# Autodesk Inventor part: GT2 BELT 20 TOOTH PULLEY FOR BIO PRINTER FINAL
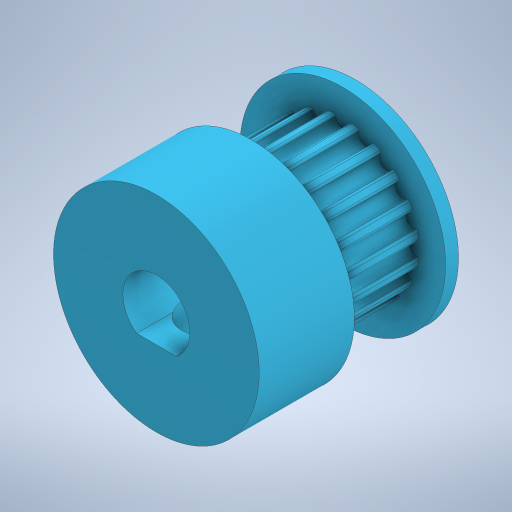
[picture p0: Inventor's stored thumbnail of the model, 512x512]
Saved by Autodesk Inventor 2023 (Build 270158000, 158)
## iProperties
Created: 2025-07
Part Number: GT2 BELT 20 TOOTH PULLEY FOR BIO PRINTER FINAL
Material: Generic
Document SubType Name: Modeling
Designer: erjon
Density: 1 g/cm^3
Appearance: Default
Author: erjon
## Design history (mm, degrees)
sketch "Sketch1" dims "d0" = 11.9
  geometry: L1 (0, 5.95)-(0, 5.2); L2 (0, 5.2)-(0, 5.755); C1 r 0.15 at (-0.705, 5.757); C2 r 0.15 at (-1.109, 5.693); C3 r 0.15 at (-2.45, 5.257); C4 r 0.15 at (-2.814, 5.072); C5 r 0.15 at (-3.954, 4.243); C6 r 0.15 at (-4.243, 3.954); C7 r 0.15 at (-5.072, 2.814); C8 r 0.15 at (-5.257, 2.45); C9 r 0.15 at (-5.693, 1.109); C10 r 0.15 at (-5.757, 0.705); C11 r 0.15 at (-5.757, -0.705); C12 r 0.15 at (-5.693, -1.109); C13 r 0.15 at (-5.257, -2.45); C14 r 0.15 at (-5.072, -2.814); C15 r 0.15 at (-4.243, -3.954); C16 r 0.15 at (-3.954, -4.243); C17 r 0.15 at (-2.814, -5.072); C18 r 0.15 at (-2.45, -5.257); C19 r 0.15 at (-1.109, -5.693); C20 r 0.15 at (-0.705, -5.757); C21 r 0.15 at (0.705, -5.757); C22 r 0.15 at (1.109, -5.693); C23 r 0.15 at (2.45, -5.257); C24 r 0.15 at (2.814, -5.072); C25 r 0.15 at (3.954, -4.243); C26 r 0.15 at (4.243, -3.954); C27 r 0.15 at (5.072, -2.814); C28 r 0.15 at (5.257, -2.45); C29 r 0.15 at (5.693, -1.109); C30 r 0.15 at (5.757, -0.705); C31 r 0.15 at (5.757, 0.705); C32 r 0.15 at (5.693, 1.109); C33 r 0.15 at (5.257, 2.45); C34 r 0.15 at (5.072, 2.814); C35 r 0.15 at (4.243, 3.954); C36 r 0.15 at (3.954, 4.243); C37 r 0.15 at (2.814, 5.072); C38 r 0.15 at (2.45, 5.257); C39 r 0.15 at (1.109, 5.693); C40 r 0.15 at (0.705, 5.757); A1 r 0.555 centre (0, 5.755) between (-0.528, 5.927) and (0.528, 5.927); A2 r 0.555 centre (-1.778, 5.473) between (-2.333, 5.473) and (-1.329, 5.8); A3 r 0.555 centre (-3.383, 4.656) between (-3.911, 4.484) and (-3.057, 5.105); A4 r 0.555 centre (-4.656, 3.383) between (-5.105, 3.057) and (-4.484, 3.911); A5 r 0.555 centre (-5.473, 1.778) between (-5.8, 1.329) and (-5.473, 2.333); A6 r 0.555 centre (-5.755, 0) between (-5.927, -0.528) and (-5.927, 0.528); A7 r 0.555 centre (-5.473, -1.778) between (-5.473, -2.333) and (-5.8, -1.329); A8 r 0.555 centre (-4.656, -3.383) between (-4.484, -3.911) and (-5.105, -3.057); A9 r 0.555 centre (-3.383, -4.656) between (-3.057, -5.105) and (-3.911, -4.484); A10 r 0.555 centre (-1.778, -5.473) between (-1.329, -5.8) and (-2.333, -5.473); A11 r 0.555 centre (0, -5.755) between (0.528, -5.927) and (-0.528, -5.927); A12 r 0.555 centre (1.778, -5.473) between (2.333, -5.473) and (1.329, -5.8); A13 r 0.555 centre (3.383, -4.656) between (3.911, -4.484) and (3.057, -5.105); A14 r 0.555 centre (4.656, -3.383) between (5.105, -3.057) and (4.484, -3.911); A15 r 0.555 centre (5.473, -1.778) between (5.8, -1.329) and (5.473, -2.333); A16 r 0.555 centre (5.755, 0) between (5.927, 0.528) and (5.927, -0.528); A17 r 0.555 centre (5.473, 1.778) between (5.473, 2.333) and (5.8, 1.329); A18 r 0.555 centre (4.656, 3.383) between (4.484, 3.911) and (5.105, 3.057); A19 r 0.555 centre (3.383, 4.656) between (3.057, 5.105) and (3.911, 4.484); A20 r 0.555 centre (1.778, 5.473) between (1.329, 5.8) and (2.333, 5.473); 101 further points
  constraints: 60 centre point, 60 point on circle, 4 end point, 2 coincident, 2 tangent, 1 point on line, 1 vertical, 189 other
  dimensions: "d1" = 0.75 distance of L1.start L1.end; "d2" = 0.555 distance of L1.end L2.end; "d5" = 360 deg dimension on point (0, 0) A1.centre (derived); "d7" = 0.3 diameter of C1; "d8" = 0.3 diameter of C2; "d11" = 360 deg dimension on point (0, 0) C1.centre (derived)
extrude "Extrusion1" new body sketch "Sketch1" distance "d13" = 7.1; taper "d14" = 0 deg
sketch "Sketch2"
  geometry: C1 r 8 at (0, 0); 1 further point
  constraints: 1 centre point, 1 coincident
  dimensions: "d15" = 16 diameter of C1
extrude "Extrusion2" join sketch "Sketch2" distance "d16" = 1; taper "d17" = 0 deg
sketch "Sketch3"
  geometry: C1 r 8 at (0, 0); 1 further point
  constraints: 1 centre point, 1 coincident
  dimensions: "d18" = 16 diameter of C1
extrude "Extrusion3" join sketch "Sketch3" distance "d19" = 7.4; taper "d20" = 0 deg
sketch "Sketch4"
  geometry: C1 r 2.5 at (0, 0); 1 further point
  constraints: 1 centre point, 1 coincident
  dimensions: "d21" = 5 diameter of C1
extrude "Extrusion4" cut sketch "Sketch4" distance "d22" = 50; taper "d23" = 0 deg
sketch "Sketch5"
  geometry: L1 (0, 2.5)-(0, -2); L2 (0, -2)-(-4.04, -2); L3 (-4.04, -2)-(4.181, -2); 5 further points
  constraints: 6 end point, 1 perpendicular, 1 point on line, 1 vertical, 2 other
  dimensions: "d24" = 4.5 distance of L1.start L1.end
extrude "Extrusion5" join sketch "Sketch5" distance "d25" = 15.5; taper "d26" = 0 deg
sketch "Sketch7"
  geometry: L1 (1.5, -2)-(-1.5, -2) reference; L2 (1.565, -2.2)-(-1.565, -2.2); A1 r 2.5 centre (0, 0) between (1.5, -2) and (-1.5, -2) reference; A2 r 2.7 centre (0, 0) between (1.565, -2.2) and (-1.565, -2.2); 1 further point
  constraints: 2 end point, 2 point on circle, 1 centre point, 1 other
  dimensions: "d27" = 0.2 radial gap between concentric circles of A1 A2
extrude "Extrusion6" cut sketch "Sketch7" distance "d28" = 20; taper "d29" = 0 deg
sketch "Sketch8"
  geometry: C1 r 2.7 at (0, 0); 1 further point
  constraints: 1 centre point, 1 coincident
extrude "Extrusion7" cut sketch "Sketch8" distance "d30" = 5; taper "d31" = 0 deg
sketch "Sketch9"
  geometry: L1 (8, 7.1)-(-8, 7.1) reference; L2 (0, 7.1)-(0, 14.5); L3 (-2.7, 14.5)-(2.7, 14.5) reference; C1 r 1.75 at (0, 10.8); 3 further points
  constraints: 3 midpoint, 2 end point, 1 centre point
  dimensions: "d32" = 3.5 diameter of C1
extrude "Extrusion8" cut sketch "Sketch9" distance "d33" = 20; taper "d34" = 0 deg
sketch "Sketch10"
  geometry: C1 r 2.7 at (0, 0); 1 further point
  constraints: 1 centre point, 1 coincident
extrude "Extrusion9" join sketch "Sketch10" distance "d35" = 15.5; taper "d36" = 0 deg
sketch "Sketch11"
  geometry: L1 (1.533, -2.1)-(-1.533, -2.1); A1 r 2.6 centre (0, 0) between (1.533, -2.1) and (-1.533, -2.1); 1 further point
  constraints: 2 end point, 2 point on circle, 1 centre point, 1 coincident
extrude "Extrusion10" cut sketch "Sketch11" distance "d40" = 20; taper "d41" = 0 deg
sketch "Sketch12"
  geometry: C1 r 2.6 at (0, 0); 1 further point
  constraints: 1 centre point, 1 coincident
extrude "Extrusion11" cut sketch "Sketch12" distance "d42" = 4; taper "d43" = 0 deg
sketch "Sketch14"
  geometry: L1 (9.533, 15.5)-(-6.467, 15.5) reference; L2 (1.533, 15.5)-(1.533, 0); L3 (-6.467, 0)-(9.533, 0) reference; L4 (6.516, 14.5)-(6.516, 7.4) reference; L5 (-6.467, 7.4)-(9.533, 7.4) reference; L6 (6.516, 7.4)-(-6.467, 7.4); L7 (1.533, 7.4)-(1.533, 0); C1 r 1.75 at (1.533, 3.7); 1 further point
  constraints: 6 end point, 3 midpoint, 2 point on line, 1 centre point, 1 collinear, 1 perpendicular
  dimensions: "d44" = 3.5 diameter of C1
extrude "Extrusion12" cut sketch "Sketch14" stored distance "d45" = 6; taper "d46" = 0 deg
body "Solid1"
